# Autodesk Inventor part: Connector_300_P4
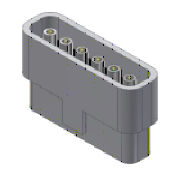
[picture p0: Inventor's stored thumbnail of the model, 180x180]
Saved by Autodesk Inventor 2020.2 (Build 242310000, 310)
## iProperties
Manager: www.cadconsulting.pl
Company: Fabian Stasiak CAD Consulting
Created: 2014-10
Part Number: Connector_300_P4
Material: Ogólny
Description: Wtyk typ 300, ALPHA
Document SubType Name: Modeling
Standard: ALPHA-100/2012
Designer: F.Stasiak
Manufacturer: ALPHA
Standards Organization: ISO
Language: pl-PL
Size Designation: Connector_300_P4
Categories: <MemberInstance><Categories><Category DisplayName="Kable i wiązki przewodów" InternalName="e4a7e005-5e42-4d16-b293-125e7f0d0512" Mnemonic="CABLEANDHARNESS"><Cat
Density: 1 g/cm^3
Appearance: Śnieg
Catalog Web Link: www.expertbooks.pl
IsCustomPart: 0
Author: F.Stasiak
Subject: Zbiór ćwiczeń. Autodesk Inventor 2020. Kurs Professional
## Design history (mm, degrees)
sketch "Szkic1"
  geometry: L1 (0, 0)-(30, 0); L2 (0, 2.5)-(20, 2.5); L3 (20, 2.5)-(20, -2.5); L4 (20, -2.5)-(0, -2.5); L5 (0, -2.5)-(0, 2.5); 7 further points
  constraints: 10 end point, 2 horizontal, 2 parallel, 1 coincident, 1 midpoint, 1 perpendicular
  dimensions: "d0" = 5 distance of point (7.5, 0) point (2.5, 0); "d1" = 5 distance of point (12.5, 0) point (7.5, 0) (= d0); "d2" = 5 distance of point (17.5, 0) point (12.5, 0) (= d0); "d3" = 5 distance of point (22.5, 0) point (17.5, 0) (= d0); "d4" = 5 distance of point (22.5, 0) point (27.5, 0) (= d0); "d16" = 2.5 distance of point (2.5, 0) L1.start; "d17" = 2.5 distance of point (27.5, 0) L1.end (= d16); "d18" = 5 distance of L4.end L2.start; "d19" = 20 distance of L3.end L4.end (= 0.5 x LPINÓW)
node "Oś konstrukcyjna1"
node "Oś konstrukcyjna2"
node "Oś konstrukcyjna3"
node "Oś konstrukcyjna4"
node "Oś konstrukcyjna5"
node "Oś konstrukcyjna6"
extrude "Wyciągnięcie proste3" new body sketch "Szkic1" distance "d20" = 3; taper "d21" = 0 deg
sketch "Szkic3"
  geometry: C1 r 1 at (2.5, 0); 2 further points
  constraints: 1 centre point, 1 coincident
  dimensions: "d22" = 2 diameter of C1
extrude "Wyciągnięcie proste4" join sketch "Szkic3" distance "d23" = 5; taper "d24" = 0 deg; dims "d29" = 15, "d30" = 0
sketch "Szkic4"
  geometry: C1 r 1.5 at (0, 0)
  constraints: 1 centre point
  dimensions: "d31" = 3 diameter of C1
extrude "Wyciągnięcie proste5" join sketch "Szkic4" stored distance "d32" = 0; taper "d33" = 0 deg
sketch "Szkic5"
  geometry: C1 r 0.9 at (0, 0)
  constraints: 1 centre point
  dimensions: "d34" = 1.8 diameter of C1
extrude "Wyciągnięcie proste6" cut sketch "Szkic5" distance "d35" = 7; taper "d36" = 0 deg
fillet "Zaokrąglenie3" dims "d45" = 1
pattern_linear "Szyk prostokątny2" dims "d27" = 5
node "Płaszczyzna konstrukcyjna1"
sketch "Szkic6"
  geometry: L1 (0, -2.5)-(20, -2.5) reference; L2 (20, -2.5)-(20, 2.5) reference; L3 (20, 2.5)-(0, 2.5) reference; L4 (0, 2.5)-(0, -2.5) reference; L5 (21.5, -4)-(-1.5, -4); L6 (-1.5, -4)-(-1.5, 4); L7 (-1.5, 4)-(21.5, 4); L8 (21.5, 4)-(21.5, -4)
  constraints: 8 end point, 3 other
  dimensions: "d37" = 1.5 distance between parallel lines of L5 L1
extrude "Wyciągnięcie proste7" join sketch "Szkic6" distance "d38" = 15.25; taper "d39" = 0 deg
fillet "Zaokrąglenie1" dims "d40" = 1
fillet "Zaokrąglenie2" dims "d41" = 2.5
chamfer "Faza1" distance "d42" = 1.05; stored, may be unused: second distance "d43" = 11, angle "d44" = 45 deg
sketch "Szkic7"
  geometry: L1 (-1.5, -1.5)-(-1.5, 1.5) reference; L2 (19, -4)-(1, -4) reference; L3 (21.5, 1.5)-(21.5, -1.5) reference; L4 (1, 4)-(19, 4) reference; L5 (-3, -1.5)-(-3, 1.5); L6 (1, 5.5)-(19, 5.5); L7 (23, 1.5)-(23, -1.5); L8 (19, -5.5)-(1, -5.5); C1 r 1.5 at (12.5, 0) reference; C2 r 1.5 at (7.5, 0) reference; C3 r 1.5 at (2.5, 0) reference; A1 r 2.5 centre (1, 1.5) between (1, 4) and (-1.5, 1.5) reference; A2 r 2.5 centre (1, -1.5) between (-1.5, -1.5) and (1, -4) reference; A3 r 2.5 centre (19, -1.5) between (19, -4) and (21.5, -1.5) reference; A4 r 2.5 centre (19, 1.5) between (21.5, 1.5) and (19, 4) reference; A5 r 4 centre (1, -1.5) between (-3, -1.5) and (1, -5.5); A6 r 4 centre (1, 1.5) between (1, 5.5) and (-3, 1.5); A7 r 4 centre (19, 1.5) between (23, 1.5) and (19, 5.5); A8 r 4 centre (19, -1.5) between (19, -5.5) and (23, -1.5)
  constraints: 8 end point, 8 point on circle, 4 centre point, 7 other
  dimensions: "d46" = 1.5 distance between parallel lines of L2 L8
extrude "Wyciągnięcie proste8" join sketch "Szkic7" stored distance "d47" = 12; taper "d48" = 0 deg
sketch "Szkic8"
  geometry: L1 (-1, 4)-(-19, 4) reference; L2 (1.5, -1.5)-(1.5, 1.5) reference; L3 (-19, -4)-(-1, -4) reference; L4 (-21.5, 1.5)-(-21.5, -1.5) reference; L5 (3, -1.5)-(3, 1.5) reference; L6 (-1, 5.5)-(-19, 5.5) reference; L7 (-23, 1.5)-(-23, -1.5) reference; L8 (-19, -5.5)-(-1, -5.5) reference; L9 (-7, -5.5)-(-13, -5.5); L10 (-13, -5.5)-(-13, -4); L11 (-13, -4)-(-7, -4); L12 (-7, -4)-(-7, -5.5); A1 r 2.5 centre (-1, 1.5) between (1.5, 1.5) and (-1, 4) reference; A2 r 2.5 centre (-1, -1.5) between (-1, -4) and (1.5, -1.5) reference; A3 r 2.5 centre (-19, -1.5) between (-21.5, -1.5) and (-19, -4) reference; A4 r 2.5 centre (-19, 1.5) between (-19, 4) and (-21.5, 1.5) reference; A5 r 4 centre (-1, -1.5) between (-1, -5.5) and (3, -1.5) reference; A6 r 4 centre (-1, 1.5) between (3, 1.5) and (-1, 5.5) reference; A7 r 4 centre (-19, 1.5) between (-19, 5.5) and (-23, 1.5) reference; A8 r 4 centre (-19, -1.5) between (-23, -1.5) and (-19, -5.5) reference; 2 further points
  constraints: 8 end point, 4 midpoint, 2 parallel, 1 horizontal, 1 perpendicular
  dimensions: "d49" = 6 distance of L9.start L9.end
extrude "Wyciągnięcie proste9" join sketch "Szkic8" distance "d50" = 6.5; taper "d51" = 0 deg
node "Punkt konstrukcyjny2"
node "Punkt konstrukcyjny3"
node "Punkt konstrukcyjny4"
node "Punkt konstrukcyjny5"
node "Punkt konstrukcyjny6"
node "Punkt konstrukcyjny7"
node "1"
node "2"
node "3"
node "4"
node "5"
node "6"
node "Bryła2"
node "Pętla rzutowana1"
node "Pętla rzutowana2"
other parameters: "d28" = 8
